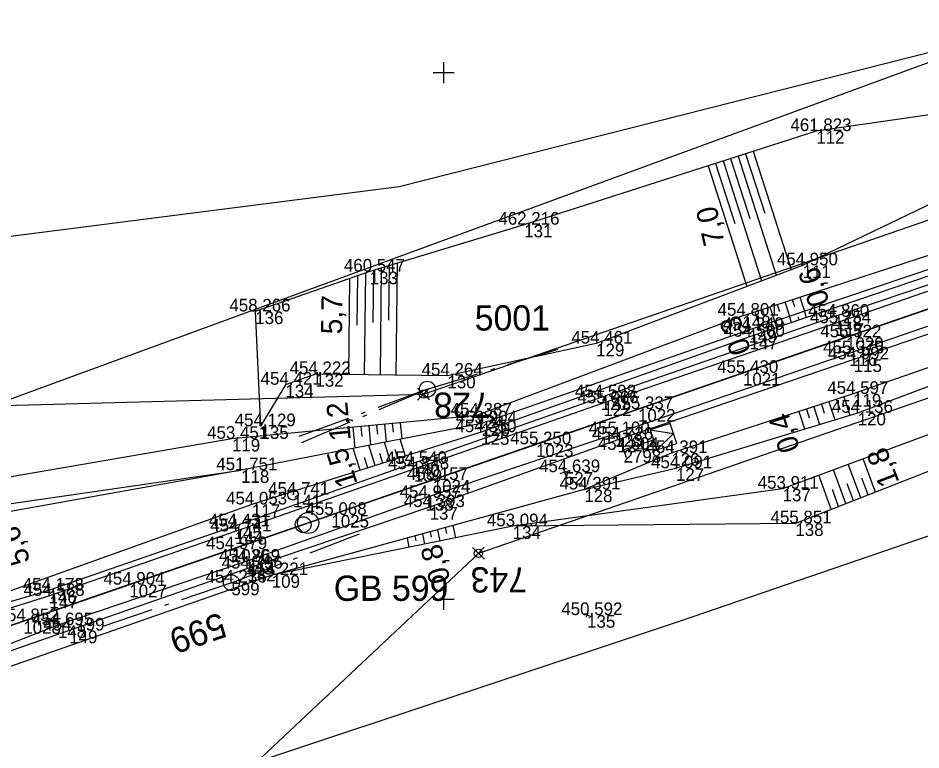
# Model space of a CAD drawing. Extents: x -776734 to -748832, y -1118122 to -976986.
# Drawn here: x -751040.4 to -750954.7, y -1114664.3 to -1114594.8 of the extents above; entities that cross this region are included whole.
import ezdxf

# ---------------------------------------------------------------- set-up
doc = ezdxf.new("R2010")
doc.units = 0
for name, color, linetype in [('KM_Hranice parcel', 7, 'Continuous'), ('Level 61 Křížky', 7, 'Continuous'), ('Obvod stavby - SŽ+ČD', 7, 'Continuous'), ('OSA', 7, 'Continuous'), ('SŽG Vrstva 1', 7, 'Continuous'), ('SŽG Vrstva 4', 7, 'Continuous'), ('SŽG Vrstva 48', 7, 'Continuous'), ('SŽG Vrstva 49', 7, 'Continuous'), ('SŽG Vrstva 53', 7, 'Continuous'), ('SŽG Vrstva 60', 7, 'Continuous'), ('SŽG Vrstva 61', 7, 'Continuous'), ('SŽG Vrstva 63', 7, 'Continuous'), ('SŽG Vrstva 7', 7, 'Continuous'), ('SŽG Vrstva 8', 7, 'Continuous'), ('Vrstva 63 ŽBP', 7, 'Continuous'), ('VYT-BODY', 7, 'Continuous')]:
    doc.layers.add(name, color=color, linetype=linetype)

msp = doc.modelspace()

# ---------------------------------------------------------------- linework, layer by layer
at = {"layer": 'KM_Hranice parcel'}
for points in [[(-751123.4, -1114617.49), (-751113.24, -1114617.58), (-751102.68, -1114616.94), (-751084.8, -1114616.01), (-751048.12, -1114616.42), (-751004.23, -1114610.82), (-750945.62, -1114595.97)], [(-751091.59, -1114651.24), (-751052.09, -1114634.98), (-750945.62, -1114595.97)], [(-750903.28, -1114626.63), (-750977.55, -1114652.09), (-751017.8, -1114665.47), (-751047.63, -1114693.52)]]:
    msp.add_lwpolyline(points, dxfattribs=at)
at = {"layer": 'Level 61 Křížky'}
for p, q in [((-751000, -1114600), (-751000, -1114599)), ((-751001, -1114600), (-750999, -1114600)), ((-751000, -1114601), (-751000, -1114600)), ((-751000, -1114650), (-751000, -1114649)), ((-751000, -1114650), (-751000, -1114649)), ((-751001, -1114650), (-750999, -1114650)), ((-751001, -1114650), (-750999, -1114650)), ((-751000, -1114651), (-751000, -1114650)), ((-751000, -1114651), (-751000, -1114650))]:
    msp.add_line(p, q, dxfattribs=at)
at = {"layer": 'Obvod stavby - SŽ+ČD'}
for points in [[(-751236.9, -1114707.02), (-751193.03, -1114664.28), (-751178.42, -1114675.26), (-751174.34, -1114678.03), (-751170.9473, -1114676.9001), (-751168.1235, -1114675.9597), (-751162.9, -1114674.22), (-751118.39, -1114659.47), (-751098.21, -1114652.66), (-751091.59, -1114651.24), (-751052.09, -1114634.98), (-751042.9845, -1114631.6438), (-751001.9301, -1114630.5149), (-750919.7259, -1114602.1536)], [(-750914.5076, -1114617.2787), (-750996.7117, -1114645.64), (-751017.8, -1114665.47), (-751047.63, -1114693.52), (-751057.9, -1114691.02), (-751081.52, -1114685.27), (-751134.08, -1114703.51), (-751142.83, -1114706.54), (-751153.31, -1114710.17), (-751148.64, -1114719.49), (-751162.24, -1114725.26), (-751172.58, -1114730.25), (-751213.65, -1114726.85)]]:
    msp.add_lwpolyline(points, dxfattribs=at)
at = {"layer": 'OSA'}
msp.add_line((-751221.2426, -1114714.6428), (-750912.9148, -1114608.268), dxfattribs=at)
msp.add_circle((-751012.8797, -1114642.7554), 1, dxfattribs=at)
at = {"layer": 'SŽG Vrstva 1'}
msp.add_lwpolyline([(-750952.239, -1114621.829), (-750961.799, -1114625.127), (-750971.586, -1114628.505), (-750981.562, -1114631.945), (-750991.246, -1114635.286), (-751001.048, -1114638.665), (-751010.672, -1114641.989), (-751020.123, -1114645.246), (-751029.869, -1114648.612), (-751039.93, -1114652.08), (-751049.798, -1114655.49)], dxfattribs=at)
at = {"layer": 'SŽG Vrstva 4'}
for p, q in [((-751037.448, -1114649.672), (-751047.485, -1114652.852)), ((-751036.639, -1114652.467), (-751046.217, -1114656.195))]:
    msp.add_line(p, q, dxfattribs=at)
for points in [[(-750909.854, -1114605.662), (-750913.632, -1114606.277), (-750928.936, -1114611.392), (-750945.448, -1114617.255), (-750962.947, -1114623.179), (-750985.088, -1114630.83), (-751003.049, -1114637.15), (-751019.956, -1114643.079), (-751037.537, -1114649.178), (-751047.428, -1114652.085)], [(-750909.854, -1114605.662), (-750913.482, -1114606.81), (-750928.752, -1114612.038), (-750945.395, -1114617.786), (-750962.769, -1114623.789), (-750984.849, -1114631.395), (-751002.837, -1114637.648), (-751019.817, -1114643.56), (-751037.448, -1114649.672)], [(-750908.397, -1114608.245), (-750913.156, -1114610.918), (-750927.279, -1114615.559), (-750944.077, -1114621.468), (-750961.07, -1114627.222), (-750983.47, -1114634.851), (-751001.346, -1114641.244), (-751018.647, -1114647.092), (-751035.567, -1114652.973), (-751044.403, -1114656.035)], [(-750908.397, -1114608.245), (-750913.028, -1114609.922), (-750927.564, -1114615.039), (-750944.227, -1114620.718), (-750961.521, -1114626.651), (-750983.784, -1114634.327), (-751001.734, -1114640.382), (-751018.892, -1114646.443), (-751036.639, -1114652.467)]]:
    msp.add_lwpolyline(points, dxfattribs=at)
at = {"layer": 'SŽG Vrstva 48'}
for p, q in [((-750971.3317, -1114607.6982), (-750969.525, -1114613.3372)), ((-750970.6175, -1114607.4694), (-750967.0159, -1114618.7102)), ((-750974.1887, -1114608.6136), (-750972.358, -1114614.3272)), ((-750973.4744, -1114608.3847), (-750969.8251, -1114619.7747)), ((-750972.7602, -1114608.1559), (-750970.9415, -1114613.8322)), ((-750972.046, -1114607.927), (-750968.4205, -1114619.2424)), ((-750974.9029, -1114608.8424), (-750971.2296, -1114620.3069)), ((-751006.6852, -1114618.7821), (-751006.7445, -1114623.7338)), ((-751005.9325, -1114618.5537), (-751006.0538, -1114628.6944)), ((-751005.1797, -1114618.3253), (-751005.2417, -1114623.5144)), ((-751004.4269, -1114618.0969), (-751004.5539, -1114628.7124)), ((-751008.9446, -1114619.553), (-751009.0535, -1114628.6586)), ((-751008.1914, -1114619.2909), (-751008.2475, -1114623.9792)), ((-751007.4382, -1114619.0287), (-751007.5537, -1114628.6765)), ((-750966.189, -1114621.305), (-750965.751, -1114622.653)), ((-750969.042, -1114622.234), (-750968.594, -1114623.61)), ((-750968.329, -1114622.002), (-750968.106, -1114622.686)), ((-750967.616, -1114621.77), (-750967.173, -1114623.131)), ((-750966.902, -1114621.537), (-750966.682, -1114622.215)), ((-750970.468, -1114622.698), (-750970.016, -1114624.089)), ((-750969.755, -1114622.466), (-750969.53, -1114623.158)), ((-750966.966, -1114623.714), (-750967.165, -1114623.129)), ((-750966.256, -1114623.473), (-750966.355, -1114623.181)), ((-750965.546, -1114623.232), (-750965.743, -1114622.65)), ((-750968.387, -1114624.196), (-750968.586, -1114623.607)), ((-750967.676, -1114623.955), (-750967.776, -1114623.661)), ((-750969.807, -1114624.678), (-750970.008, -1114624.086)), ((-750969.097, -1114624.437), (-750969.197, -1114624.142)), ((-750961.9966, -1114630.7873), (-750961.4344, -1114632.5169)), ((-750964.8497, -1114631.7146), (-750964.3043, -1114633.3927)), ((-750964.1364, -1114631.4828), (-750963.8616, -1114632.3283)), ((-750963.4231, -1114631.2509), (-750962.8693, -1114632.9548)), ((-750962.7099, -1114631.0191), (-750962.4309, -1114631.8775)), ((-750966.2762, -1114632.1782), (-750965.7392, -1114633.8306)), ((-750965.5629, -1114631.9464), (-750965.2923, -1114632.779)), ((-751006.384, -1114633.46), (-751006.301, -1114634.335)), ((-751005.637, -1114633.389), (-751005.478, -1114635.066)), ((-751004.89, -1114633.318), (-751004.814, -1114634.12)), ((-751004.144, -1114633.248), (-751003.998, -1114634.778)), ((-751008.624, -1114633.673), (-751008.437, -1114635.643)), ((-751007.877, -1114633.602), (-751007.787, -1114634.55)), ((-751007.13, -1114633.531), (-751006.957, -1114635.354)), ((-751005.076, -1114636.854), (-751005.629, -1114635.096)), ((-751003.645, -1114636.403), (-751004.148, -1114634.807)), ((-751007.937, -1114637.755), (-751008.593, -1114635.673)), ((-751006.506, -1114637.305), (-751007.111, -1114635.384)), ((-751004.36, -1114636.628), (-751004.624, -1114635.79)), ((-751007.222, -1114637.53), (-751007.537, -1114636.529)), ((-751005.791, -1114637.079), (-751006.081, -1114636.16)), ((-750959.009, -1114639.816), (-750960.177, -1114636.667)), ((-750961.804, -1114640.91), (-750962.99, -1114637.71)), ((-750960.406, -1114640.363), (-750961.584, -1114637.188)), ((-750963.201, -1114641.456), (-750964.397, -1114638.231)), ((-750959.708, -1114640.09), (-750960.294, -1114638.509)), ((-750961.105, -1114640.636), (-750961.696, -1114639.043)), ((-750962.502, -1114641.183), (-750963.098, -1114639.577)), ((-751002.0319, -1114643.7902), (-751001.8335, -1114644.7684)), ((-751001.3069, -1114643.5916), (-751001.2027, -1114644.1054)), ((-751000.5819, -1114643.3929), (-751000.3635, -1114644.4703)), ((-750999.8569, -1114643.1943), (-750999.7427, -1114643.7578)), ((-750999.132, -1114642.9957), (-750998.8934, -1114644.1722)), ((-751003.4819, -1114644.1875), (-751003.3036, -1114645.0665)), ((-751002.7569, -1114643.9888), (-751002.6627, -1114644.4531))]:
    msp.add_line(p, q, dxfattribs=at)
at = {"layer": 'SŽG Vrstva 49'}
for p, q in [((-750996.896, -1114632.559), (-750996.404, -1114633.299)), ((-751058.95, -1114643.469), (-751019.246, -1114637.748)), ((-750967.828, -1114639.504), (-750993.458, -1114643.07)), ((-750966.612, -1114642.791), (-750993.458, -1114643.07)), ((-750993.458, -1114643.07), (-751016.335, -1114647.709)), ((-750986.1662, -1114651.6104), (-750986.6158, -1114651.3916)), ((-750986.2816, -1114651.2762), (-750986.5004, -1114651.7258))]:
    msp.add_line(p, q, dxfattribs=at)
for points in [[(-750914.284, -1114599.037), (-750918.732, -1114597.886), (-750932.03, -1114599.468), (-750940.019, -1114601.94), (-750946.634, -1114602.952), (-750964.627, -1114605.55), (-750992.361, -1114614.436), (-751007.031, -1114618.887), (-751017.906, -1114622.672), (-751017.405, -1114633.573)], [(-750914.284, -1114599.037), (-750918.793, -1114599.925), (-750945.255, -1114608.376), (-750965.923, -1114618.296), (-750985.53, -1114625.726), (-750999.654, -1114628.771), (-751012.193, -1114628.621), (-751015.037, -1114629.632), (-751017.405, -1114633.573)], [(-750971.64, -1114623.079), (-750922.658, -1114607.141), (-750911.92, -1114603.429)], [(-750912.493, -1114604.315), (-750923.138, -1114608.3), (-750971.049, -1114624.437)], [(-750911.848, -1114604.924), (-750922.676, -1114608.685), (-750970.963, -1114625.07)], [(-750907.433, -1114611.535), (-750909.429, -1114611.74), (-750926.275, -1114617.369), (-750943.057, -1114624.185), (-750961.128, -1114630.505), (-750978.395, -1114636.117), (-750986.658, -1114639.578), (-751016.335, -1114647.709)], [(-750986.658, -1114639.578), (-750977.954, -1114637.558), (-750960.694, -1114632.291), (-750942.145, -1114625.351), (-750926.015, -1114618.435), (-750909.195, -1114613.036), (-750906.794, -1114617.513)], [(-750906.794, -1114617.513), (-750919.397, -1114621.544), (-750967.828, -1114639.504)], [(-750904.524, -1114618.563), (-750918.921, -1114624.132), (-750966.612, -1114642.791)], [(-750971.64, -1114623.079), (-750996.896, -1114632.559), (-751020.117, -1114634.765)], [(-750971.049, -1114624.437), (-750996.404, -1114633.299), (-751019.246, -1114637.748)], [(-750970.963, -1114625.07), (-750996.446, -1114634.135), (-751018.226, -1114640.997), (-751047.344, -1114651.414), (-751047.645, -1114652.397)], [(-751020.117, -1114634.765), (-751060.04, -1114641.62), (-751070.127, -1114648.352), (-751076.528, -1114658.314), (-751078.11, -1114663.715)], [(-751019.246, -1114637.748), (-751058.49, -1114644.759), (-751068.921, -1114649.956), (-751075.459, -1114658.878), (-751078.11, -1114663.715)], [(-751016.335, -1114647.709), (-751044.621, -1114657.572), (-751046.052, -1114656.653)]]:
    msp.add_lwpolyline(points, dxfattribs=at)
at = {"layer": 'SŽG Vrstva 53'}
for points in [[(-751091.59, -1114651.24), (-751052.09, -1114634.98), (-750945.62, -1114595.97), (-750923.65, -1114590.78), (-750909.46, -1114590.94), (-750904.52, -1114591.74), (-750900.07, -1114579.45), (-750884.93, -1114572.87), (-750860.41, -1114581.47), (-750789.41, -1114554.45)], [(-750804.97, -1114584.92), (-750894.76, -1114611.21), (-750899.97, -1114614.15), (-750906.35, -1114617.75), (-750903.28, -1114626.63), (-750977.55, -1114652.09), (-751017.8, -1114665.47), (-751047.63, -1114693.52)]]:
    msp.add_lwpolyline(points, dxfattribs=at)
at = {"layer": 'SŽG Vrstva 60'}
for p, q in [((-750964.627, -1114605.55), (-750964.627, -1114605.55)), ((-750992.361, -1114614.436), (-750992.361, -1114614.436)), ((-751007.031, -1114618.887), (-751007.031, -1114618.887)), ((-750965.923, -1114618.296), (-750965.923, -1114618.296)), ((-751017.906, -1114622.672), (-751017.906, -1114622.672)), ((-750971.64, -1114623.079), (-750971.64, -1114623.079)), ((-750962.947, -1114623.179), (-750962.947, -1114623.179)), ((-750962.769, -1114623.789), (-750962.769, -1114623.789)), ((-750971.049, -1114624.437), (-750971.049, -1114624.437)), ((-750985.53, -1114625.726), (-750985.53, -1114625.726)), ((-750970.963, -1114625.07), (-750970.963, -1114625.07)), ((-750961.799, -1114625.127), (-750961.799, -1114625.127)), ((-750961.521, -1114626.651), (-750961.521, -1114626.651)), ((-750961.07, -1114627.222), (-750961.07, -1114627.222)), ((-751012.193, -1114628.621), (-751012.193, -1114628.621)), ((-750999.654, -1114628.771), (-750999.654, -1114628.771)), ((-750971.586, -1114628.505), (-750971.586, -1114628.505)), ((-751015.037, -1114629.632), (-751015.037, -1114629.632)), ((-750985.088, -1114630.83), (-750985.088, -1114630.83)), ((-750961.128, -1114630.505), (-750961.128, -1114630.505)), ((-750984.849, -1114631.395), (-750984.849, -1114631.395)), ((-750996.896, -1114632.559), (-750996.896, -1114632.559)), ((-750981.562, -1114631.945), (-750981.562, -1114631.945)), ((-750960.694, -1114632.291), (-750960.694, -1114632.291)), ((-750996.404, -1114633.299), (-750996.404, -1114633.299)), ((-751017.405, -1114633.573), (-751017.405, -1114633.573)), ((-750996.446, -1114634.135), (-750996.446, -1114634.135)), ((-750983.784, -1114634.327), (-750983.784, -1114634.327)), ((-751020.117, -1114634.765), (-751020.117, -1114634.765)), ((-750983.47, -1114634.851), (-750983.47, -1114634.851)), ((-750991.246, -1114635.286), (-750991.246, -1114635.286)), ((-750982.921, -1114635.817), (-750982.921, -1114635.817)), ((-750978.395, -1114636.117), (-750978.395, -1114636.117)), ((-751019.246, -1114637.748), (-751019.246, -1114637.748)), ((-751003.049, -1114637.15), (-751003.049, -1114637.15)), ((-751002.837, -1114637.648), (-751002.837, -1114637.648)), ((-750977.954, -1114637.558), (-750977.954, -1114637.558)), ((-750988.5, -1114637.931), (-750988.5, -1114637.931)), ((-751001.048, -1114638.665), (-751001.048, -1114638.665)), ((-750967.828, -1114639.504), (-750967.828, -1114639.504)), ((-751014.322, -1114640.079), (-751014.322, -1114640.079)), ((-750986.658, -1114639.578), (-750986.658, -1114639.578)), ((-751018.226, -1114640.997), (-751018.226, -1114640.997)), ((-751001.734, -1114640.382), (-751001.734, -1114640.382)), ((-751010.672, -1114641.989), (-751010.672, -1114641.989)), ((-751001.346, -1114641.244), (-751001.346, -1114641.244)), ((-750966.612, -1114642.791), (-750966.612, -1114642.791)), ((-751019.956, -1114643.079), (-751019.956, -1114643.079)), ((-751019.817, -1114643.56), (-751019.817, -1114643.56)), ((-750993.458, -1114643.07), (-750993.458, -1114643.07)), ((-751020.123, -1114645.246), (-751020.123, -1114645.246)), ((-751018.892, -1114646.443), (-751018.892, -1114646.443)), ((-751018.647, -1114647.092), (-751018.647, -1114647.092)), ((-751016.335, -1114647.709), (-751016.335, -1114647.709)), ((-751029.869, -1114648.612), (-751029.869, -1114648.612)), ((-751020.168, -1114648.425), (-751020.168, -1114648.425)), ((-751037.537, -1114649.178), (-751037.537, -1114649.178)), ((-751037.448, -1114649.672), (-751037.448, -1114649.672)), ((-750986.391, -1114651.501), (-750986.391, -1114651.501)), ((-751039.93, -1114652.08), (-751039.93, -1114652.08)), ((-751036.639, -1114652.467), (-751036.639, -1114652.467)), ((-751035.567, -1114652.973), (-751035.567, -1114652.973))]:
    msp.add_line(p, q, dxfattribs=at)
at = {"layer": 'SŽG Vrstva 63'}
msp.add_line((-751020.1207, -1114648.4087), (-751020.2153, -1114648.4413), dxfattribs=at)
msp.add_circle((-751020.168, -1114648.425), 0.756, dxfattribs=at)
at = {"layer": 'SŽG Vrstva 7'}
for p, q in [((-750988.0273, -1114637.7679), (-750988.9727, -1114638.0941)), ((-750988.3369, -1114638.4037), (-750988.6631, -1114637.4583)), ((-751014.2747, -1114640.0627), (-751014.3693, -1114640.0953))]:
    msp.add_line(p, q, dxfattribs=at)
for centre, radius in [((-751014.322, -1114640.079), 0.5), ((-751013.3487, -1114642.9115), 0.75)]:
    msp.add_circle(centre, radius, dxfattribs=at)
at = {"layer": 'SŽG Vrstva 8'}
msp.add_line((-750983.1563, -1114635.1049), (-750982.6857, -1114636.5291), dxfattribs=at)
for points in [[(-750982.921, -1114635.817), (-750980.0725, -1114634.8757), (-750979.7587, -1114635.8252), (-750977.8597, -1114635.1977), (-750978.4872, -1114633.2987), (-750980.3862, -1114633.9262), (-750980.0725, -1114634.8757)], [(-750980.3862, -1114633.9262), (-750978.1735, -1114634.2482), (-750979.7587, -1114635.8252)]]:
    msp.add_lwpolyline(points, dxfattribs=at)
at = {"layer": 'Vrstva 63 ŽBP'}
for p, q in [((-750993.9093, -1114627.7093), (-750989.1298, -1114626.2409)), ((-750995.5343, -1114628.2085), (-750995.1519, -1114628.0911)), ((-751001.5565, -1114630.0587), (-750996.777, -1114628.5903)), ((-751001.5565, -1114630.0587), (-751006.2472, -1114631.7901)), ((-751001.5565, -1114630.0587), (-751006.1572, -1114632.0166)), ((-751001.5971, -1114630.0295), (-751001.5159, -1114630.088)), ((-751007.4667, -1114632.2403), (-751007.842, -1114632.3788)), ((-751007.3534, -1114632.5256), (-751007.7215, -1114632.6823)), ((-751009.0616, -1114632.8289), (-751013.7522, -1114634.5603)), ((-751008.9177, -1114633.1913), (-751013.5184, -1114635.1492)), ((-751012.691, -1114645.58), (-751008.0179, -1114643.8018)), ((-751014.2799, -1114646.1846), (-751013.906, -1114646.0423)), ((-751020.168, -1114648.4252), (-751015.4949, -1114646.6469)), ((-751020.168, -1114648.4249), (-751024.8997, -1114650.0409)), ((-751020.1786, -1114648.3761), (-751020.1574, -1114648.4739)), ((-751026.1299, -1114650.4611), (-751026.5084, -1114650.5904)), ((-751027.7386, -1114651.0106), (-751032.4703, -1114652.6266))]:
    msp.add_line(p, q, dxfattribs=at)
for centre in [(-751001.5565, -1114630.0587), (-751020.168, -1114648.425)]:
    msp.add_circle(centre, 0.756, dxfattribs=at)
at = {"layer": 'VYT-BODY'}
for p, q in [((-751002.5027, -1114629.9572), (-751001.3554, -1114631.0724)), ((-751001.3714, -1114629.9412), (-751002.4867, -1114631.0884)), ((-750997.2843, -1114645.0823), (-750996.1371, -1114646.1975)), ((-750996.1531, -1114645.0663), (-750997.2683, -1114646.2135))]:
    msp.add_line(p, q, dxfattribs=at)
for centre in [(-751001.929, -1114630.5148), (-750996.7107, -1114645.6399)]:
    msp.add_circle(centre, 0.4, dxfattribs=at)

# ---------------------------------------------------------------- texts
at = {"layer": 'Obvod stavby - SŽ+ČD'}
for s, p in [('728', (-750995.6156, -1114630.3754)), ('743', (-750992.0974, -1114646.9573))]:
    msp.add_text(s, height=2.4, rotation=180, dxfattribs=at).set_placement(p)
at = {"layer": 'SŽG Vrstva 48'}
for s, rotation, p in [('7,0', 102.765508, (-750973.3126, -1114616.1694)), ('0,6', 108.024102, (-750963.336, -1114621.828)), ('5,7', 89.190246, (-751009.6599, -1114624.8554)), ('0,3', 108.743374, (-750970.792, -1114626.411)), ('1,2', 95.426825, (-751008.821, -1114634.885)), ('0,4', 108.004837, (-750966.16, -1114635.7005)), ('1,5', 107.487538, (-751008.166, -1114639.012)), ('1,8', 111.367814, (-750956.699, -1114638.87)), ('5,6', 109.684732, (-751039.239, -1114646.369)), ('0,8', 105.322076, (-750999.3408, -1114648.1994))]:
    msp.add_text(s, height=2, rotation=rotation, dxfattribs=at).set_placement(p)
at = {"layer": 'SŽG Vrstva 60'}
for s, p in [('112', (-750964.627, -1114606.75)), ('131', (-750992.361, -1114615.636)), ('133', (-751007.031, -1114620.087)), ('111', (-750965.923, -1114619.496)), ('136', (-751017.906, -1114623.872)), ('148', (-750971.64, -1114624.279)), ('118', (-750962.947, -1114624.379)), ('117', (-750962.769, -1114624.989)), ('149', (-750971.049, -1114625.637)), ('129', (-750985.53, -1114626.926)), ('147', (-750970.963, -1114626.27)), ('1020', (-750961.799, -1114626.327)), ('116', (-750961.521, -1114627.851)), ('115', (-750961.07, -1114628.422)), ('132', (-751012.193, -1114629.821)), ('130', (-750999.654, -1114629.971)), ('1021', (-750971.586, -1114629.705)), ('134', (-751015.037, -1114630.832)), ('121', (-750985.088, -1114632.03)), ('119', (-750961.128, -1114631.705)), ('122', (-750984.849, -1114632.595)), ('124', (-750996.896, -1114633.759)), ('1022', (-750981.562, -1114633.145)), ('120', (-750960.694, -1114633.491)), ('126', (-750996.404, -1114634.499)), ('135', (-751017.405, -1114634.773)), ('125', (-750996.446, -1114635.335)), ('123', (-750983.784, -1114635.527)), ('119', (-751020.117, -1114635.965)), ('124', (-750983.47, -1114636.051)), ('1023', (-750991.246, -1114636.486)), ('2798', (-750982.921, -1114637.017)), ('126', (-750978.395, -1114637.317)), ('118', (-751019.246, -1114638.948)), ('140', (-751003.049, -1114638.35)), ('139', (-751002.837, -1114638.848)), ('127', (-750977.954, -1114638.758)), ('1024', (-751001.048, -1114639.865)), ('527', (-750988.5, -1114639.131)), ('137', (-750967.828, -1114640.704)), ('141', (-751014.322, -1114641.279)), ('138', (-751001.734, -1114641.582)), ('128', (-750986.658, -1114640.778)), ('117', (-751018.226, -1114642.197)), ('137', (-751001.346, -1114642.444)), ('1025', (-751010.672, -1114643.189)), ('138', (-750966.612, -1114643.991)), ('145', (-751019.956, -1114644.279)), ('144', (-751019.817, -1114644.76)), ('134', (-750993.458, -1114644.27)), ('1026', (-751020.123, -1114646.446)), ('143', (-751018.892, -1114647.643)), ('142', (-751018.647, -1114648.292)), ('109', (-751016.335, -1114648.909)), ('1027', (-751029.869, -1114649.812)), ('599', (-751020.168, -1114649.625)), ('146', (-751037.537, -1114650.378)), ('147', (-751037.448, -1114650.872)), ('135', (-750986.391, -1114652.701)), ('1028', (-751039.93, -1114653.28)), ('148', (-751036.639, -1114653.667)), ('149', (-751035.567, -1114654.173))]:
    msp.add_text(s, height=1.2, dxfattribs=at).set_placement(p)
at = {"layer": 'SŽG Vrstva 61'}
for s, p in [('461.823', (-750967.0789, -1114605.55)), ('462.216', (-750994.8129, -1114614.436)), ('454.950', (-750968.374, -1114618.296)), ('460.547', (-751009.4829, -1114618.887)), ('458.266', (-751020.3579, -1114622.672)), ('454.801', (-750973.9974, -1114623.079)), ('454.860', (-750965.398, -1114623.179)), ('454.249', (-750973.5027, -1114624.437)), ('455.254', (-750965.22, -1114623.789)), ('454.500', (-750973.414, -1114625.07)), ('455.522', (-750964.2472, -1114625.127)), ('454.461', (-750987.8874, -1114625.726)), ('455.375', (-750963.9771, -1114626.651)), ('454.992', (-750963.5182, -1114627.222)), ('454.222', (-751014.6412, -1114628.621)), ('455.430', (-750974.037, -1114628.505)), ('454.264', (-751002.105, -1114628.771)), ('454.421', (-751017.3944, -1114629.632)), ('454.598', (-750987.5417, -1114630.83)), ('454.597', (-750963.5799, -1114630.505)), ('455.066', (-750987.3009, -1114631.395)), ('455.337', (-750984.0139, -1114631.945)), ('454.387', (-750999.3479, -1114632.559)), ('454.136', (-750963.1459, -1114632.291)), ('454.129', (-751019.8587, -1114633.573)), ('453.904', (-750998.855, -1114633.299)), ('454.350', (-750998.897, -1114634.135)), ('455.100', (-750986.235, -1114634.327)), ('453.451', (-751022.4744, -1114634.765)), ('455.250', (-750993.697, -1114635.286)), ('454.726', (-750985.9219, -1114634.851)), ('454.604', (-750985.372, -1114635.817)), ('454.391', (-750980.7524, -1114636.117)), ('454.540', (-751005.5, -1114637.15)), ('451.751', (-751021.6034, -1114637.748)), ('454.848', (-751005.2907, -1114637.648)), ('454.639', (-750990.9537, -1114637.931)), ('454.091', (-750980.3114, -1114637.558)), ('455.157', (-751003.4999, -1114638.665)), ('454.391', (-750989.0154, -1114639.578)), ('453.911', (-750970.1854, -1114639.504)), ('454.741', (-751016.6794, -1114640.079)), ('454.957', (-751004.1859, -1114640.382)), ('454.053', (-751020.6779, -1114640.997)), ('454.393', (-751003.7979, -1114641.244)), ('455.068', (-751013.1257, -1114641.989)), ('454.431', (-751022.3134, -1114643.079)), ('453.094', (-750995.909, -1114643.07)), ('455.851', (-750968.9694, -1114642.791)), ('454.741', (-751022.1744, -1114643.56)), ('454.979', (-751022.5767, -1114645.246)), ('454.869', (-751021.3457, -1114646.443)), ('454.396', (-751021.0989, -1114647.092)), ('454.236', (-751022.6199, -1114648.425)), ('454.221', (-751018.6924, -1114647.709)), ('454.178', (-751039.9907, -1114649.178)), ('454.904', (-751032.32, -1114648.612)), ('454.588', (-751039.9017, -1114649.672)), ('450.592', (-750988.8392, -1114651.501)), ('454.852', (-751042.3782, -1114652.08)), ('454.695', (-751039.0951, -1114652.467)), ('454.199', (-751038.0207, -1114652.973))]:
    msp.add_text(s, height=1.2, dxfattribs=at).set_placement(p)
at = {"layer": 'SŽG Vrstva 63'}
msp.add_text('599', height=2.4, rotation=199.060063, dxfattribs=at).set_placement((-751021.2053, -1114651.2138))
at = {"layer": 'Vrstva 63 ŽBP'}
for s, p in [('5001', (-750997.0601, -1114624.4867)), ('GB 599', (-751010.4491, -1114650.152))]:
    msp.add_text(s, height=2.4, dxfattribs=at).set_placement(p)

doc.saveas('drawing.dxf')
